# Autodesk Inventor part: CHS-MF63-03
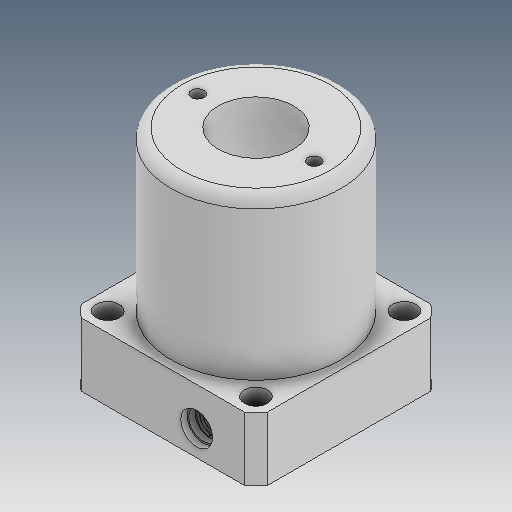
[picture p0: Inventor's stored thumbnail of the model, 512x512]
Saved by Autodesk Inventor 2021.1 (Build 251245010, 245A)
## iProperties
Created: 2019-05
Part Number: CHS-MF63-03
Material: Ogólny
Document SubType Name: Modeling
Designer: user
Density: 1 g/cm^3
Appearance: Domyślna
Author: user
Revision Number: ÈÎºÎ
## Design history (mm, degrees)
feature "ÊäÈë1"
node "Bryła1"
